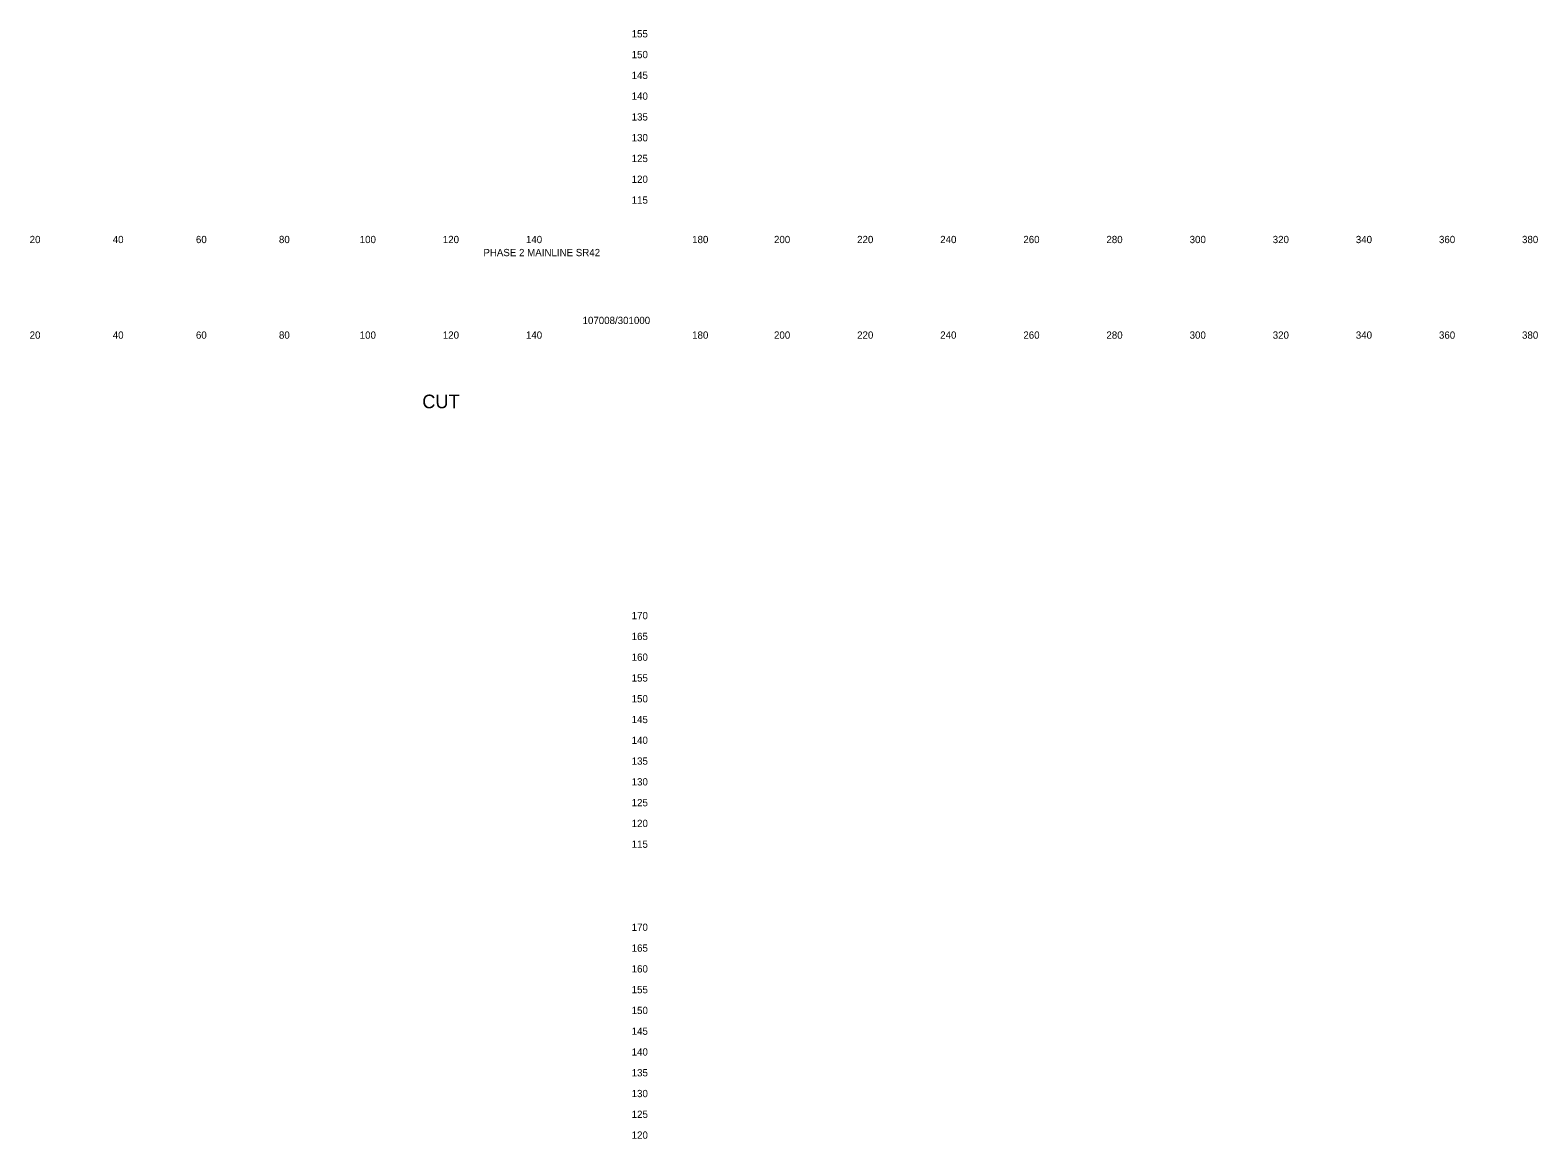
# Model space of a CAD drawing. Extents: x 21281 to 22024, y 6472 to 15208.
# Drawn here: x 21661.4 to 22024.2, y 13849.8 to 14116.6 of the extents above; entities that cross this region are included whole.
import ezdxf

# ---------------------------------------------------------------- set-up
doc = ezdxf.new("R2010")
doc.units = 0
doc.layers.add('XS_SHEET_LABELS_ELEVATION', color=7, linetype='Continuous')
doc.layers.add('XS_SHEET_LABELS_OFFSET', color=7, linetype='Continuous')

msp = doc.modelspace()

# ---------------------------------------------------------------- texts
at = {"layer": 'XS_SHEET_LABELS_ELEVATION'}
for s, p in [('  155  ', (21804.84, 14114.84)), ('  150  ', (21804.84, 14109.84)), ('  145  ', (21804.84, 14104.84)), ('  140  ', (21804.84, 14099.84)), ('  135  ', (21804.84, 14094.84)), ('  130  ', (21804.84, 14089.84)), ('  125  ', (21804.84, 14084.84)), ('  120  ', (21804.84, 14079.84)), ('  115  ', (21804.84, 14074.84)), ('  170  ', (21804.84, 13974.84)), ('  165  ', (21804.84, 13969.84)), ('  160  ', (21804.84, 13964.84)), ('  155  ', (21804.84, 13959.84)), ('  150  ', (21804.84, 13954.84)), ('  145  ', (21804.84, 13949.84)), ('  140  ', (21804.84, 13944.84)), ('  135  ', (21804.84, 13939.84)), ('  130  ', (21804.84, 13934.84)), ('  125  ', (21804.84, 13929.84)), ('  120  ', (21804.84, 13924.84)), ('  115  ', (21804.84, 13919.84)), ('  170  ', (21804.84, 13899.84)), ('  165  ', (21804.84, 13894.84)), ('  160  ', (21804.84, 13889.84)), ('  155  ', (21804.84, 13884.84)), ('  150  ', (21804.84, 13879.84)), ('  145  ', (21804.84, 13874.84)), ('  140  ', (21804.84, 13869.84)), ('  135  ', (21804.84, 13864.84)), ('  130  ', (21804.84, 13859.84)), ('  125  ', (21804.84, 13854.84)), ('  120  ', (21804.84, 13849.84))]:
    msp.add_text(s, height=1.75, dxfattribs=at).set_placement(p)
at = {"layer": 'XS_SHEET_LABELS_OFFSET'}
for s, height, p in [('  20  ', 1.75, (21659.95, 14065.34)), ('  40  ', 1.75, (21679.95, 14065.34)), ('  60  ', 1.75, (21699.97, 14065.34)), ('  80  ', 1.75, (21719.95, 14065.34)), ('  100  ', 1.75, (21739.39, 14065.34)), ('  120  ', 1.75, (21759.39, 14065.34)), ('  140  ', 1.75, (21779.39, 14065.34)), ('  180  ', 1.75, (21819.39, 14065.34)), ('  200  ', 1.75, (21839.1, 14065.34)), ('  220  ', 1.75, (21859.1, 14065.34)), ('  240  ', 1.75, (21879.1, 14065.34)), ('  260  ', 1.75, (21899.11, 14065.34)), ('  280  ', 1.75, (21919.1, 14065.34)), ('  300  ', 1.75, (21939.13, 14065.34)), ('  320  ', 1.75, (21959.13, 14065.34)), ('  340  ', 1.75, (21979.13, 14065.34)), ('  360  ', 1.75, (21999.14, 14065.34)), ('  380  ', 1.75, (22019.13, 14065.34)), ('PHASE 2 MAINLINE SR42', 1.75, (21770.45, 14062.2)), ('107008/301000', 1.75, (21794.32, 14045.87)), ('  20  ', 1.75, (21659.95, 14042.34)), ('  40  ', 1.75, (21679.95, 14042.34)), ('  60  ', 1.75, (21699.97, 14042.34)), ('  80  ', 1.75, (21719.95, 14042.34)), ('  100  ', 1.75, (21739.39, 14042.34)), ('  120  ', 1.75, (21759.39, 14042.34)), ('  140  ', 1.75, (21779.39, 14042.34)), ('  180  ', 1.75, (21819.39, 14042.34)), ('  200  ', 1.75, (21839.1, 14042.34)), ('  220  ', 1.75, (21859.1, 14042.34)), ('  240  ', 1.75, (21879.1, 14042.34)), ('  260  ', 1.75, (21899.11, 14042.34)), ('  280  ', 1.75, (21919.1, 14042.34)), ('  300  ', 1.75, (21939.13, 14042.34)), ('  320  ', 1.75, (21959.13, 14042.34)), ('  340  ', 1.75, (21979.13, 14042.34)), ('  360  ', 1.75, (21999.14, 14042.34)), ('  380  ', 1.75, (22019.13, 14042.34)), ('CUT', 3.273, (21755.74, 14025.61))]:
    msp.add_text(s, height=height, dxfattribs=at).set_placement(p)

doc.saveas('drawing.dxf')
